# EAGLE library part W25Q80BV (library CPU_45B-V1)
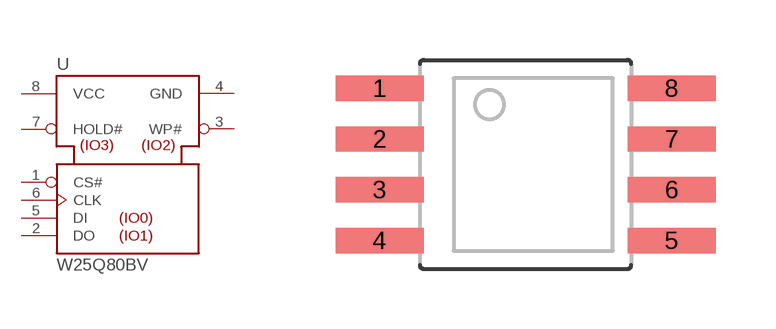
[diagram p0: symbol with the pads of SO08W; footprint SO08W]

Designator prefix U

## W25Q80BVSSIG  [SO08W]
1  CS#  in
2  DO
3  WP#
4  GND  pwr
5  DI
6  CLK
7  HOLD#
8  VCC  pwr

## Footprint SO08W (pad centres in mm)
SMALL OUTLINE INTEGRATED CIRCUIT 8-Lead, 0.208" Body, Plastic Small Outline Package (EIAJ)
smd 2.2 x 0.635: 1 -3.651,1.905; 2 -3.651,0.635; 3 -3.651,-0.635; 4 -3.651,-1.905; 5 3.651,-1.905; 6 3.651,-0.635; 7 3.651,0.635; 8 3.651,1.905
